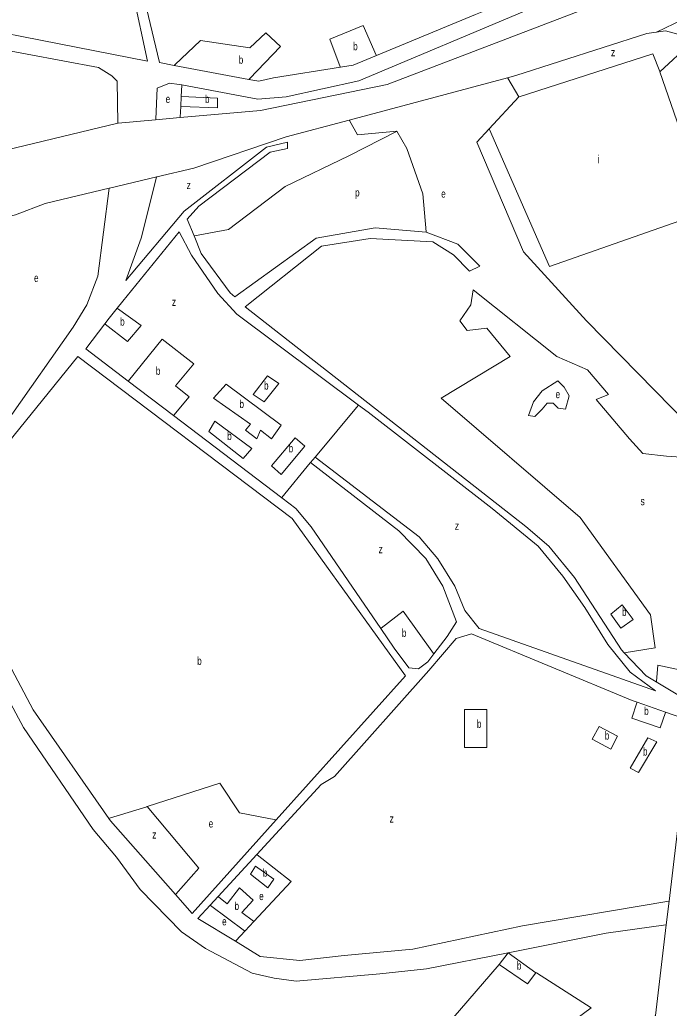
# Model space of a CAD drawing. Extents: x 639657 to 671642, y 222838 to 252123.
# Drawn here: x 646133 to 646943, y 234105 to 235340 of the extents above; entities that cross this region are included whole.
import ezdxf

# ---------------------------------------------------------------- set-up
doc = ezdxf.new("R2010")
doc.units = 0
doc.header["$LTSCALE"] = 4
doc.layers.add('1', color=7, linetype='Continuous', lineweight=13)
doc.layers.add('21', color=7, linetype='Continuous', lineweight=13)
doc.layers.add('7', color=7, linetype='Continuous')

msp = doc.modelspace()

# ---------------------------------------------------------------- linework, layer by layer
at = {"layer": '1'}
msp.add_line((646355.064, 234217.207), (646401.779, 234188.645), dxfattribs=at)
for points in [[(646274.127, 235371.606), (646292.24, 235288.07), (645956.71, 235353.74), (645928.56, 235742.53), (645923.92, 235762.48), (645929.11, 235827.2), (645931.11, 235920.48), (645922.95, 235989.19), (645934.57, 235985.14), (646044.18, 235918.37), (646077.46, 235923.3), (646144.99, 235951.43), (646168.02, 235910.74), (646221.42, 235860.99), (646229.75, 235868.35), (646175.52, 235915.08), (646147.13, 235958.96), (646112.99, 235946.51), (646075.06, 235928.87)], [(646325.478, 235282.776), (646307.09, 235286.23), (646272.66, 235431.29), (646278.55, 235486.56), (646270.55, 235562.8), (646255.09, 235595.58), (646207.67, 235686.2), (646208.89, 235698.45), (646334.37, 235807.31), (646327.44, 235816.5), (646230.37, 235734.68), (646187.18, 235837.14), (646172.39, 235829.53), (646193, 235800), (646218.39, 235725.37), (646196.88, 235692.79), (646236.77, 235611.943)], [(646912.55, 235423.56), (646767.823, 235352.575), (646555.881, 235263.456), (646465.268, 235243.481), (646429.944, 235240.408), (646334.933, 235258.231)], [(646927.135, 235324.15), (646927.635, 235324.388), (646960.334, 235339.941), (647121.629, 235416.66)], [(646332.798, 235217.634), (646433.016, 235226.579), (646591.205, 235258.847), (646934.018, 235390.256)], [(646780.621, 235381.923), (646767.14, 235373.04), (646743.016, 235363.107), (646701.706, 235346.098), (646577.884, 235295.114)], [(645963.427, 235329.862), (646231.04, 235280.18), (646247.65, 235269.54), (646254.36, 235263.13), (646255.11, 235210.7), (645754.01, 235089.69)], [(646931.74, 235274.76), (646970.42, 235310.66), (646969.08, 235317.75), (646938.73, 235325.94), (646927.135, 235324.15)], [(646927.135, 235324.15), (646915.54, 235322.36), (646751.87, 235270.01), (646741.659, 235267.28), (646544.019, 235214.445), (646465.014, 235193.324)], [(646577.884, 235295.114), (646548.9, 235283.18), (646532.933, 235280.605)], [(646532.933, 235280.605), (646449.27, 235267.11), (646431.24, 235262.91), (646418.728, 235265.26), (646325.478, 235282.776)], [(646989.415, 235099.809), (646961.64, 235166.84), (646967.19, 235172.68), (646931.74, 235274.76)], [(646334.933, 235258.231), (646331.652, 235258.847), (646319.365, 235260.383), (646304.007, 235254.237), (646302.243, 235215.405), (646302.22, 235214.904)], [(646255.11, 235210.7), (646255.61, 235210.745), (646302.22, 235214.904), (646332.798, 235217.634)], [(646303.601, 235143.423), (646350.082, 235154.362), (646465.014, 235193.324)], [(646265.013, 235013.897), (646337.795, 235100.584), (646440.695, 235180.483), (646466.804, 235186.63)], [(646466.804, 235186.63), (646466.804, 235178.947), (646445.302, 235174.337), (646356.13, 235106.87), (646341.61, 235090.67), (646350.105, 235069.717)], [(646244.01, 235129.4), (646244.51, 235129.518), (646303.601, 235143.423)], [(646303.601, 235143.423), (646303.473, 235142.924), (646284.041, 235066.78), (646265.013, 235013.897)], [(646119.84, 234842.62), (646051.98, 235076.66), (646127.3, 235096.25), (646164.18, 235110.01), (646244.01, 235129.4)], [(646244.01, 235129.4), (646229.86, 235019.29), (646216.11, 234983.53), (646199.09, 234955.92), (646119.84, 234842.62)], [(646400.89, 234993.46), (646502.53, 235066.93), (646576.17, 235079.84), (646639.82, 235074.21)], [(646555.524, 234858.302), (646403.39, 234971.99), (646380.02, 234997.85), (646347.05, 235045.57), (646331.61, 235074.7), (646261.147, 234988.289), (646254.204, 234979.573)], [(646350.105, 235069.717), (646359.08, 235047.58), (646395.27, 234998.59), (646400.89, 234993.46)], [(646639.82, 235074.21), (646679.46, 235059.62), (646707.14, 235031.85), (646694.07, 235025.75), (646673.95, 235046.05), (646648.28, 235062.23), (646570.23, 235066.48), (646509.47, 235057.09), (646413.86, 234981.08), (646764.39, 234706.84), (646793.13, 234682.3), (646825.18, 234643.17), (646883.78, 234552.63), (646887.227, 234548.986)], [(646254.204, 234979.573), (646244.109, 234966.902), (646238.837, 234959.962)], [(646238.837, 234959.962), (646214.929, 234928.489), (646267.829, 234888.279), (646324.487, 234845.212), (646459.644, 234742.478), (646477.27, 234729.08)], [(646614.164, 234520.24), (646472.69, 234716.77), (646204.86, 234919.26), (646029.641, 234702.821)], [(646501.43, 234793.36), (646631.22, 234694), (646654.6, 234666.21), (646675.66, 234632.38), (646688.32, 234601.94), (646706.08, 234579.27), (646926.22, 234501.31), (646894.48, 234524.75), (646866.97, 234559.4), (646837.88, 234605.64), (646810.77, 234644.8), (646779.81, 234682.22), (646722.34, 234729.35), (646567.41, 234849.42), (646555.524, 234858.302)], [(646649.628, 234547.675), (646666.38, 234569.36), (646677.87, 234587.48), (646660.83, 234632.29), (646639.55, 234666.98), (646606.03, 234701.37), (646495.45, 234786.88), (646501.43, 234793.36)], [(646477.27, 234729.08), (646496.38, 234706.51), (646583.382, 234579.364)], [(646029.641, 234702.821), (646149.435, 234477.749), (646243.9, 234342.178)], [(646477.553, 234138.71), (646450.23, 234142.77), (646422.68, 234149.05), (646364.46, 234179.86), (646334.67, 234200.52), (646282.76, 234253.5), (646253.28, 234293.72), (646224.26, 234328.36), (646137.07, 234455.7), (646015.52, 234682.319)], [(646583.382, 234579.364), (646600.06, 234554.99), (646618.26, 234530.39), (646630.31, 234529.17), (646641.86, 234537.62), (646649.628, 234547.675)], [(646897.191, 234489.305), (646696.45, 234572.77), (646677.36, 234567.06), (646643.478, 234526.836)], [(646887.227, 234548.986), (646914.5, 234520.15), (646927.332, 234512.556), (646954.163, 234496.678)], [(646643.478, 234526.836), (646525.61, 234394.44), (646508.7, 234384.45), (646428.368, 234297.003), (646380.213, 234244.584), (646370.261, 234233.75), (646355.064, 234217.207)], [(646347.751, 234223.362), (646452.835, 234340.462), (646614.164, 234520.24)], [(646943.317, 234238.668), (646970.08, 234463.97), (646938.884, 234474.813), (646903.312, 234487.177), (646897.191, 234489.305)], [(646243.9, 234342.178), (646245.889, 234339.323), (646326.819, 234247.191), (646347.751, 234223.362)], [(646482.161, 234164.832), (646537.45, 234170.978), (646623.456, 234178.66), (646760.143, 234207.854), (646942.816, 234238.584), (646943.317, 234238.668)], [(646749.27, 233999.6), (646771.37, 234032.75), (646808.43, 234018.15), (646872.55, 234041.32), (646911.69, 234071.21), (646926.37, 234096.01), (646939.809, 234209.137), (646943.317, 234238.668)], [(646742.205, 234174.317), (646864.579, 234198.635), (646939.308, 234209.067), (646939.809, 234209.137)], [(646401.779, 234188.645), (646432.891, 234169.623), (646482.161, 234164.832)], [(646477.553, 234138.71), (646581.989, 234147.93), (646640.35, 234154.076), (646742.204, 234174.316), (646742.205, 234174.317)]]:
    msp.add_lwpolyline(points, dxfattribs=at)
at = {"layer": '21'}
msp.add_line((646310.149, 234940.781), (646350.081, 234910.05), dxfattribs=at)
for points in [[(646532.933, 235280.605), (646532.743, 235281.105), (646519.645, 235315.502), (646561.112, 235332.404), (646577.659, 235295.614), (646577.884, 235295.114)], [(646418.728, 235265.26), (646419.209, 235265.76), (646458.212, 235306.283), (646439.782, 235323.185), (646419.817, 235304.746), (646358.384, 235313.965), (646325.978, 235283.25), (646325.478, 235282.776)], [(646755.537, 235243.48), (646756.037, 235243.641), (646922.941, 235297.258), (646931.544, 235275.26), (646931.74, 235274.76)], [(646755.537, 235243.48), (646741.951, 235266.78), (646741.659, 235267.28)], [(646334.933, 235258.231), (646334.918, 235257.935), (646334.168, 235243.68), (646333.53, 235231.559)], [(646334.168, 235243.68), (646334.668, 235243.661), (646379.262, 235241.945), (646379.262, 235229.653), (646334.03, 235231.538), (646333.53, 235231.559)], [(647015.445, 234785.175), (647010.535, 234790.175), (646840.007, 234963.83), (646761.68, 235049.876), (646703.319, 235186.628), (646718.662, 235203.332), (646755.537, 235243.48)], [(646333.53, 235231.559), (646332.824, 235218.134), (646332.798, 235217.634)], [(646544.019, 235214.445), (646544.297, 235213.945), (646554.345, 235195.849), (646603.491, 235200.458)], [(646718.662, 235203.332), (646718.881, 235202.832), (646793.933, 235031.438), (646988.915, 235099.634), (646989.415, 235099.809)], [(646603.491, 235200.458), (646602.991, 235200.201), (646543.594, 235169.728), (646463.732, 235131.314), (646393.084, 235077.536), (646350.605, 235069.808), (646350.105, 235069.717)], [(646603.491, 235200.458), (646615.778, 235178.947), (646635.743, 235122.095), (646639.777, 235074.71), (646639.82, 235074.21)], [(646887.227, 234548.986), (646926.013, 234555.112), (646919.869, 234596.599), (646832.328, 234717.985), (646658.781, 234867.029), (646744.786, 234919.271), (646715.606, 234954.611), (646691.033, 234951.538), (646681.818, 234963.83), (646695.64, 234983.805), (646698.712, 235002.244), (646803.147, 234919.271), (646841.543, 234902.369), (646867.652, 234871.638), (646852.294, 234865.492), (646893.761, 234816.323), (646910.655, 234797.885), (646939.835, 234794.812), (646958.265, 234793.275)], [(646254.204, 234979.573), (646254.704, 234979.206), (646284.041, 234957.683), (646267.147, 234937.708), (646239.337, 234959.569), (646238.837, 234959.962)], [(646310.149, 234940.781), (646268.232, 234888.779), (646267.829, 234888.279)], [(646350.081, 234910.05), (646327.043, 234882.393), (646343.937, 234868.564), (646324.903, 234845.712), (646324.487, 234845.212)], [(646501.43, 234793.36), (646501.846, 234793.86), (646555.108, 234857.802), (646555.524, 234858.302)], [(646495.45, 234786.88), (646495.047, 234786.38), (646459.965, 234742.876), (646459.644, 234742.478)], [(646649.628, 234547.675), (646649.269, 234548.175), (646611.169, 234601.207), (646583.882, 234579.757), (646583.382, 234579.364)], [(646927.332, 234512.556), (646927.374, 234513.056), (646929.084, 234533.601), (646958.265, 234527.455), (646954.23, 234497.178), (646954.163, 234496.678)], [(646903.312, 234487.177), (646903.147, 234486.677), (646896.831, 234467.528), (646932.154, 234455.236), (646938.712, 234474.313), (646938.884, 234474.813)], [(646291.72, 234356.898), (646382.333, 234386.092), (646406.906, 234349.216), (646452.335, 234340.557), (646452.835, 234340.462)], [(646291.72, 234356.898), (646291.22, 234356.744), (646244.4, 234342.332), (646243.9, 234342.178)], [(646326.819, 234247.191), (646327.266, 234247.691), (646356.224, 234280.072), (646291.72, 234356.898)], [(646428.368, 234297.003), (646428.868, 234296.61), (646471.41, 234263.17), (646424.992, 234213.49), (646413.824, 234201.536)], [(646406.906, 234255.487), (646391.548, 234235.512), (646380.713, 234244.184), (646380.213, 234244.584)], [(646406.906, 234255.487), (646423.8, 234240.122), (646409.977, 234224.756), (646424.492, 234213.865), (646424.992, 234213.49)], [(646370.261, 234233.75), (646370.761, 234233.38), (646413.324, 234201.906), (646413.824, 234201.536)], [(646413.824, 234201.536), (646402.246, 234189.145), (646401.779, 234188.645)], [(646742.204, 234174.317), (646742.204, 234174.316), (646730.988, 234159.802)], [(646742.204, 234174.317), (646742.205, 234174.317), (646777.038, 234149.466)], [(646730.988, 234159.802), (646663.388, 234081.091), (646666.46, 234064.189), (646695.64, 234031.921), (646734.036, 234022.702), (646846.15, 234105.675), (646777.538, 234149.149), (646777.038, 234149.466)], [(646777.038, 234149.466), (646766.288, 234135.638), (646730.988, 234159.802)]]:
    msp.add_lwpolyline(points, dxfattribs=at)
for points in [[(646441.761, 234894.998), (646423.8, 234871.637), (646437.622, 234862.418), (646456.052, 234885.466)], [(646390.06, 234884.644), (646374.654, 234867.027), (646420.728, 234834.76), (646414.585, 234827.077), (646428.407, 234816.322), (646433.015, 234827.077), (646446.837, 234816.322), (646459.124, 234833.224)], [(646804.428, 234888.797), (646784.718, 234876.248), (646773.967, 234862.419), (646767.824, 234845.517), (646775.503, 234843.981), (646784.718, 234853.2), (646790.861, 234860.882), (646798.54, 234860.882), (646804.683, 234854.736), (646813.898, 234853.2), (646818.506, 234870.102), (646812.362, 234880.857)], [(646376.296, 234838.522), (646422.264, 234804.029), (646411.513, 234791.737), (646368.51, 234825.541)], [(646476.398, 234817.312), (646446.837, 234782.518), (646459.124, 234771.762), (646488.304, 234807.103)], [(646870.422, 234597.115), (646883.01, 234579.697), (646898.368, 234590.452), (646884.546, 234608.891)], [(646687.96, 234478.284), (646715.605, 234478.284), (646715.605, 234430.652), (646687.96, 234430.652)], [(646855.96, 234457.109), (646878.786, 234444.864), (646870.339, 234428.731), (646847.302, 234441.023)], [(646916.797, 234442.944), (646894.528, 234404.915), (646905.279, 234399.537), (646927.932, 234437.951)], [(646426.688, 234282.326), (646449.909, 234266.243), (646442.23, 234255.487), (646420.728, 234272.389)]]:
    msp.add_lwpolyline(points, close=True, dxfattribs=at)

# ---------------------------------------------------------------- texts
at = {"layer": '7'}
for s, width, p in [('b', 0.75, (646548.825, 235301.673)), ('z', 0.8, (646870.723, 235294.185)), ('b', 0.75, (646405.994, 235284.771)), ('e', 0.75, (646314.758, 235235.799)), ('b', 0.75, (646363.904, 235235.799)), ('z', 0.8, (646340.867, 235128.241)), ('p', 0.75, (646551.273, 235119.022)), ('e', 0.75, (646658.781, 235117.484)), ('e', 0.75, (646150.425, 235012.23)), ('z', 0.8, (646322.436, 234982.267)), ('b', 0.75, (646257.932, 234957.683)), ('b', 0.75, (646302.47, 234896.221)), ('b', 0.75, (646437.622, 234877.783)), ('e', 0.75, (646801.612, 234867.029)), ('b', 0.75, (646406.906, 234854.735)), ('b', 0.75, (646391.548, 234814.785)), ('b', 0.75, (646468.338, 234799.42)), ('s', 0.8, (646907.583, 234733.35)), ('z', 0.8, (646675.674, 234702.618)), ('z', 0.8, (646580.453, 234673.424)), ('b', 0.75, (646884.546, 234595.062)), ('b', 0.75, (646609.634, 234568.94)), ('b', 0.75, (646354.116, 234533.9)), ('b', 0.75, (646912.191, 234471.37)), ('b', 0.75, (646703.318, 234455.236)), ('b', 0.75, (646863.044, 234440.64)), ('b', 0.75, (646910.655, 234420.665)), ('e', 0.75, (646368.51, 234330.777)), ('z', 0.8, (646594.275, 234336.923)), ('z', 0.8, (646297.863, 234316.948)), ('b', 0.75, (646436.086, 234269.316)), ('b', 0.75, (646400.763, 234227.829)), ('e', 0.75, (646431.479, 234240.122)), ('e', 0.75, (646385.206, 234208.557)), ('b', 0.75, (646753.233, 234153.308))]:
    msp.add_text(s, height=10, dxfattribs=dict(at, width=width)).set_placement(p)
msp.add_text('i', height=10, dxfattribs=at).set_placement((646853.829, 235160.507))

doc.saveas('drawing.dxf')
